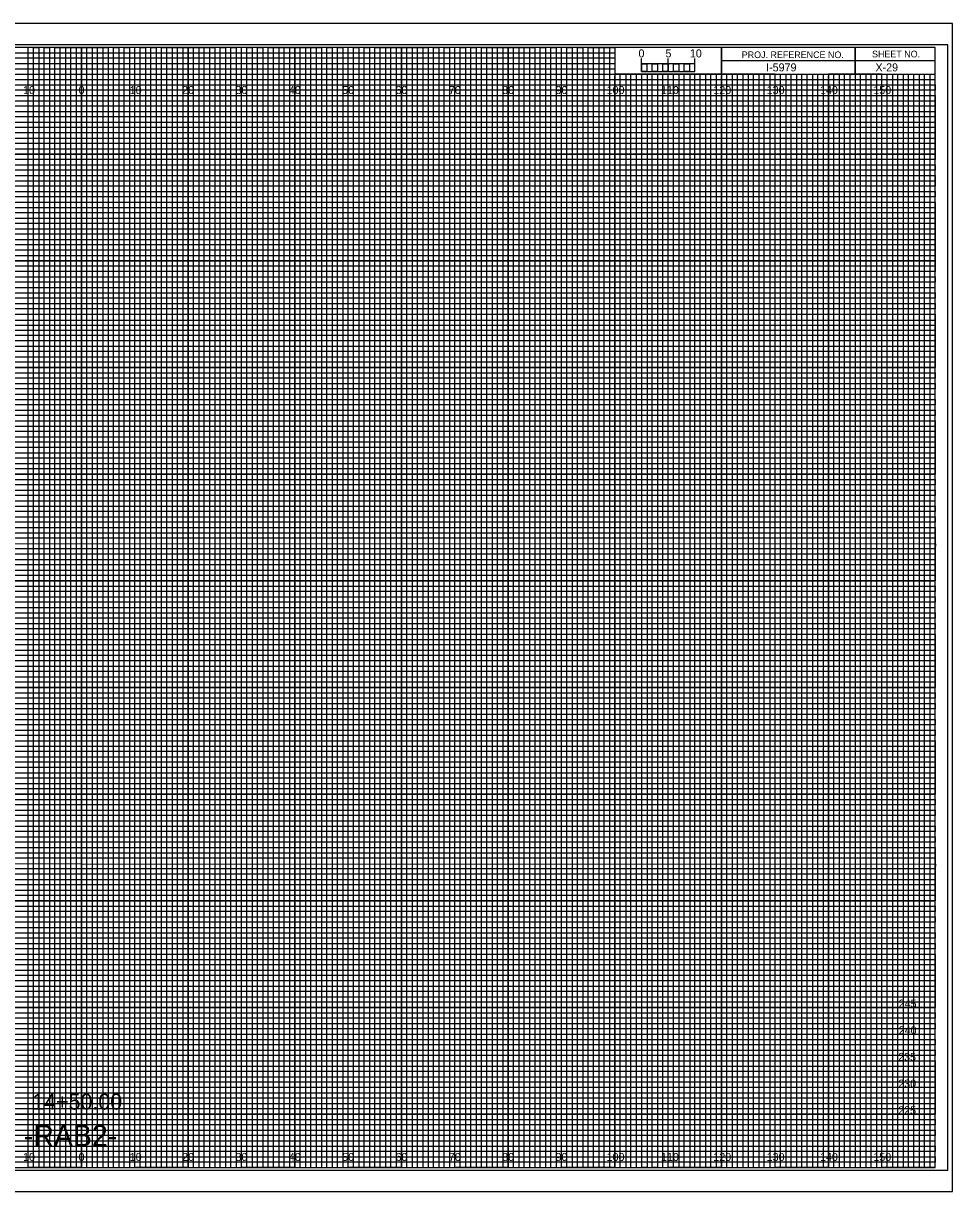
# Model space of a CAD drawing. Extents: x -13 to 323, y -5 to 654.
# Drawn here: x 149.1 to 323.3, y 435.5 to 654.5 of the extents above; entities that cross this region are included whole.
import ezdxf

# ---------------------------------------------------------------- set-up
doc = ezdxf.new("R2010")
doc.units = 0
for name, color, linetype in [('Exist CMT Pavement', 7, 'Continuous'), ('Exist Cross Section Cell', 7, 'Continuous'), ('Exist XS Center Line Elevation Label', 7, 'Continuous'), ('Exist XS Ground Line', 7, 'Continuous'), ('Prop CMT Conc Surface', 7, 'Continuous'), ('Prop CMT Concrete Structures', 7, 'Continuous'), ('Prop CMT DNC', 7, 'Continuous'), ('Prop CMT Pvmt Course 1 CG', 7, 'Continuous'), ('Prop CMT Pvmt Course 1 Wedge', 7, 'Continuous'), ('Prop CMT Pvmt Course 2', 7, 'Continuous'), ('Prop CMT Pvmt Course 2 Wedge', 7, 'Continuous'), ('Prop CMT Pvmt Course 3', 7, 'Continuous'), ('Prop CMT Pvmt Course 3 Wedge', 7, 'Continuous'), ('Prop CMT Pvmt Surface', 7, 'Continuous'), ('Prop CMT Shear Line', 7, 'Continuous'), ('Prop CMT Slope Grass', 7, 'Continuous'), ('Prop CMT Subgrade Earthwork', 7, 'Continuous')]:
    doc.layers.add(name, color=color, linetype=linetype)

msp = doc.modelspace()

# ---------------------------------------------------------------- linework, layer by layer
at = {"layer": 'Exist XS Center Line Elevation Label'}
for points in [[(145, 440), (155, 440), (155, 650), (165, 650), (165, 440), (175, 440), (175, 650), (185, 650), (185, 440), (195, 440), (195, 650), (205, 650), (205, 440), (215, 440), (215, 650), (225, 650), (225, 440), (235, 440), (235, 650), (245, 650), (245, 440), (255, 440), (255, 650), (259.93, 650), (260, 650), (260, 645), (264.99, 645), (264.99, 440), (275, 440), (275, 645), (285, 645), (285, 440), (295, 440), (295, 645), (305, 645), (305, 440), (315, 440), (315, 645)], [(0, 645), (275, 645)], [(0, 625), (320, 625), (320, 635), (0, 635)], [(0, 605), (320, 605), (320, 615), (0, 615)], [(0, 585), (320, 585), (320, 595), (0, 595)], [(0, 565), (320, 565), (320, 575), (0, 575)], [(0, 545), (320, 545), (320, 555), (0, 555)], [(0, 525), (320, 525), (320, 535), (0, 535)], [(0, 505), (320, 505), (320, 515), (0, 515)], [(0, 485), (320, 485), (320, 495), (0, 495)], [(0, 465), (320, 465), (320, 475), (0, 475)], [(0, 445), (320, 445), (320, 455), (0, 455)]]:
    msp.add_lwpolyline(points, dxfattribs=at)
at = {"layer": 'Exist XS Ground Line'}
for p, q in [((150, 650), (140, 650)), ((150, 440), (150, 650)), ((170, 650), (160, 650)), ((160, 650), (160, 440)), ((170, 440), (170, 650)), ((190, 650), (180, 650)), ((180, 650), (180, 440)), ((190, 440), (190, 650)), ((210, 650), (200, 650)), ((200, 650), (200, 440)), ((210, 440), (210, 650)), ((230, 650), (220, 650)), ((220, 650), (220, 440)), ((230, 440), (230, 650)), ((250, 650), (240, 650)), ((240, 650), (240, 440)), ((250, 440), (250, 650)), ((260, 650), (260, 440)), ((270, 440), (270, 645)), ((290, 645), (280, 645)), ((280, 645), (280, 440)), ((290, 440), (290, 645)), ((310, 645), (300, 645)), ((300, 645), (300, 440)), ((310, 440), (310, 645)), ((160, 440), (150, 440)), ((180, 440), (170, 440)), ((200, 440), (190, 440)), ((220, 440), (210, 440)), ((240, 440), (230, 440)), ((260, 440), (250, 440)), ((280, 440), (270, 440)), ((300, 440), (290, 440)), ((320, 440), (310, 440)), ((320, 440), (320, 440))]:
    msp.add_line(p, q, dxfattribs=at)
for points in [[(0, 640), (320, 640), (320, 630), (0, 630)], [(0, 620), (320, 620), (320, 610), (0, 610)], [(0, 600), (320, 600), (320, 590), (0, 590)], [(0, 580), (320, 580), (320, 570), (0, 570)], [(0, 560), (320, 560), (320, 550), (0, 550)], [(0, 540), (320, 540), (320, 530), (0, 530)], [(0, 520), (320, 520), (320, 510), (0, 510)], [(0, 500), (320, 500), (320, 490), (0, 490)], [(0, 480), (320, 480), (320, 470), (0, 470)], [(0, 460), (320, 460), (320, 450), (0, 450)]]:
    msp.add_lwpolyline(points, dxfattribs=at)
at = {"layer": 'Prop CMT Conc Surface'}
msp.add_lwpolyline([(-13.4, 435.5), (323.3, 435.5), (323.3, 654.5), (-13.4, 654.5)], close=True, dxfattribs=at)
at = {"layer": 'Prop CMT Concrete Structures'}
for p, q in [((305, 650), (305, 645)), ((305, 645), (305, 650)), ((280, 647.5), (280, 645)), ((320, 647.49), (280, 647.49)), ((280, 645), (320, 645))]:
    msp.add_line(p, q, dxfattribs=at)
for points in [[(320, 650), (0, 650), (0, 440), (320, 440)], [(280, 650), (260, 650), (260, 645.03), (280, 645.03)], [(320, 650), (280, 650), (280, 645), (320, 645)]]:
    msp.add_lwpolyline(points, close=True, dxfattribs=at)
at = {"layer": 'Prop CMT DNC'}
for p, q in [((267, 645), (266.01, 645)), ((266.01, 645), (266.01, 440)), ((267, 440), (267, 645)), ((269, 645), (268, 645)), ((268, 645), (268, 440)), ((269, 440), (269, 645)), ((266.01, 440), (265, 440)), ((268, 440), (267, 440))]:
    msp.add_line(p, q, dxfattribs=at)
for points in [[(150, 440), (151, 440), (151, 650), (152, 650), (152, 440)], [(152, 440), (153, 440), (153, 650), (154, 650), (154, 440)], [(155, 440), (156, 440), (156, 650), (157, 650), (157, 440)], [(157, 440), (158, 440), (158, 650), (159, 650), (159, 440)], [(160, 440), (161, 440), (161, 650), (162, 650), (162, 440)], [(162, 440), (163, 440), (163, 650), (164, 650), (164, 440)], [(165, 440), (166, 440), (166, 650), (167, 650), (167, 440)], [(167, 440), (168, 440), (168, 650), (169, 650), (169, 440)], [(170, 440), (171, 440), (171, 650), (172, 650), (172, 440)], [(172, 440), (173, 440), (173, 650), (174, 650), (174, 440)], [(175, 440), (176, 440), (176, 650), (177, 650), (177, 440)], [(177, 440), (178, 440), (178, 650), (179, 650), (179, 440)], [(180, 440), (181, 440), (181, 650), (182, 650), (182, 440)], [(182, 440), (183, 440), (183, 650), (184, 650), (184, 440)], [(185, 440), (186, 440), (186, 650), (187, 650), (187, 440)], [(187, 440), (188, 440), (188, 650), (189, 650), (189, 440)], [(190, 440), (191, 440), (191, 650), (192, 650), (192, 440)], [(192, 440), (193, 440), (193, 650), (194, 650), (194, 440)], [(195, 440), (196, 440), (196, 650), (197, 650), (197, 440)], [(197, 440), (198, 440), (198, 650), (199, 650), (199, 440)], [(200, 440), (201, 440), (201, 650), (202, 650), (202, 440)], [(202, 440), (203, 440), (203, 650), (204, 650), (204, 440)], [(205, 440), (206, 440), (206, 650), (207, 650), (207, 440)], [(207, 440), (208, 440), (208, 650), (209, 650), (209, 440)], [(210, 440), (211, 440), (211, 650), (212, 650), (212, 440)], [(212, 440), (213, 440), (213, 650), (214, 650), (214, 440)], [(215, 440), (216, 440), (216, 650), (217, 650), (217, 440)], [(217, 440), (218, 440), (218, 650), (219, 650), (219, 440)], [(220, 440), (221, 440), (221, 650), (222, 650), (222, 440)], [(222, 440), (223, 440), (223, 650), (224, 650), (224, 440)], [(225, 440), (226, 440), (226, 650), (227, 650), (227, 440)], [(227, 440), (228, 440), (228, 650), (229, 650), (229, 440)], [(230, 440), (231, 440), (231, 650), (232, 650), (232, 440)], [(232, 440), (233, 440), (233, 650), (234, 650), (234, 440)], [(235, 440), (236, 440), (236, 650), (237, 650), (237, 440)], [(237, 440), (238, 440), (238, 650), (239, 650), (239, 440)], [(240, 440), (241, 440), (241, 650), (242, 650), (242, 440)], [(242, 440), (243, 440), (243, 650), (244, 650), (244, 440)], [(245, 440), (246, 440), (246, 650), (247, 650), (247, 440)], [(247, 440), (248, 440), (248, 650), (249, 650), (249, 440)], [(250, 440), (251, 440), (251, 650), (252, 650), (252, 440)], [(252, 440), (253, 440), (253, 650), (254, 650), (254, 440)], [(255, 440), (256, 440), (256, 650), (257, 650), (257, 440)], [(257, 440), (258, 440), (258, 650), (259, 650), (259, 440)], [(260, 440), (261, 440), (261, 645), (262.02, 645), (262.02, 440)], [(262, 440), (263, 440), (263, 645), (263.99, 645), (263.99, 440)], [(270, 440), (270.98, 440), (270.98, 645), (272, 645), (272, 440)], [(272, 440), (273, 440), (273, 645), (274.05, 645), (274.05, 440)], [(275, 440), (276, 440), (276, 645), (277, 645), (277, 440)], [(277, 440), (278, 440), (278, 645), (279, 645), (279, 440)], [(280, 440), (281, 440), (281, 645), (282, 645), (282, 440)], [(282, 440), (283, 440), (283, 645), (284, 645), (284, 440)], [(285, 440), (286, 440), (286, 645), (287, 645), (287, 440)], [(287, 440), (288, 440), (288, 645), (289, 645), (289, 440)], [(290, 440), (291, 440), (291, 645), (292, 645), (292, 440)], [(292, 440), (293, 440), (293, 645), (294, 645), (294, 440)], [(295, 440), (296, 440), (296, 645), (297, 645), (297, 440)], [(297, 440), (298, 440), (298, 645), (299, 645), (299, 440)], [(300, 440), (301, 440), (301, 645), (302, 645), (302, 440)], [(302, 440), (303, 440), (303, 645), (304, 645), (304, 440)], [(305, 440), (306, 440), (306, 645), (307, 645), (307, 440)], [(307, 440), (308, 440), (308, 645), (309, 645), (309, 440)], [(310, 440), (311, 440), (311, 645), (312, 645), (312, 440)], [(312, 440), (313, 440), (313, 645), (314, 645), (314, 440)], [(315, 440), (316, 440), (316, 645), (317, 645), (317, 440)], [(317, 440), (318, 440), (318, 645), (319, 645), (319, 440)]]:
    msp.add_lwpolyline(points, dxfattribs=at)
at = {"layer": 'Prop CMT Pvmt Course 1 Wedge'}
for p, q in [((323.3, 654.5), (-13.4, 654.5)), ((-13.4, 435.5), (323.3, 435.5))]:
    msp.add_line(p, q, dxfattribs=at)
at = {"layer": 'Prop CMT Pvmt Course 2'}
msp.add_lwpolyline([(-10.8, 439.5), (322.4, 439.5), (322.4, 650.5), (-10.8, 650.5)], close=True, dxfattribs=at)
at = {"layer": 'Prop CMT Pvmt Course 3'}
for p, q in [((150, 440), (150, 650)), ((160, 440), (160, 650)), ((170, 440), (170, 650)), ((180, 440), (180, 650)), ((190, 440), (190, 650)), ((200, 440), (200, 650)), ((210, 440), (210, 650)), ((220, 440), (220, 650)), ((230, 440), (230, 650)), ((240, 440), (240, 650)), ((250, 440), (250, 650)), ((260, 440), (260, 644.69)), ((270, 440), (270, 644.69)), ((280, 440), (280, 644.69)), ((290, 440), (290, 644.69)), ((300, 440), (300, 644.69)), ((310, 440), (310, 644.69)), ((0, 640), (320, 640)), ((0, 630), (320, 630)), ((0, 620), (320, 620)), ((0, 610), (320, 610)), ((0, 600), (320, 600)), ((0, 590), (320, 590)), ((0, 580), (320, 580)), ((0, 570), (320, 570)), ((0, 560), (320, 560)), ((0, 550), (320, 550)), ((0, 540), (320, 540)), ((0, 530), (320, 530)), ((0, 520), (320, 520)), ((0, 510), (320, 510)), ((0, 500), (320, 500)), ((0, 490), (320, 490)), ((0, 480), (320, 480)), ((0, 470), (320, 470)), ((0, 460), (320, 460)), ((0, 450), (320, 450))]:
    msp.add_line(p, q, dxfattribs=at)
at = {"layer": 'Prop CMT Slope Grass'}
for p, q in [((265, 645.49), (265, 647.9)), ((265, 646.9), (265, 647.9)), ((270, 645.49), (270, 647.9)), ((275, 645.49), (275, 647.9)), ((275, 646.9), (275, 647.9))]:
    msp.add_line(p, q, dxfattribs=at)
for points in [[(275, 646.9), (265, 646.9), (265, 645.49), (275, 645.49)], [(265, 646.9), (266, 646.9), (266, 645.49), (265, 645.49)], [(267, 646.9), (268, 646.9), (268, 645.49), (267, 645.49)], [(269, 646.9), (270, 646.9), (270, 645.49), (269, 645.49)], [(271, 646.9), (272, 646.9), (272, 645.49), (271, 645.49)], [(273, 646.9), (274, 646.9), (274, 645.49), (273, 645.49)]]:
    msp.add_lwpolyline(points, close=True, dxfattribs=at)
at = {"layer": 'Prop CMT Subgrade Earthwork'}
for p, q in [((0, 649), (260, 649)), ((260, 649), (260, 647.98)), ((260, 647.98), (0, 647.98)), ((0, 647), (260, 647)), ((260, 647), (260, 645.89)), ((260, 645.89), (0, 645.89)), ((0, 644), (320, 644))]:
    msp.add_line(p, q, dxfattribs=at)
for points in [[(0, 643), (270, 643), (320, 643), (320, 642), (0, 642)], [(0, 641), (320, 641), (320, 639), (0, 639)], [(0, 638), (320, 638), (320, 637), (0, 636.98)], [(0, 636), (320, 636), (320, 634), (0, 634)], [(0, 633), (320, 633), (320, 632), (0, 632)], [(0, 631), (320, 631), (320, 629), (0, 629)], [(0, 628), (320, 628), (320, 627), (0, 627)], [(0, 626), (320, 626), (320, 624), (0, 624)], [(0, 623), (320, 623), (320, 622), (0, 622)], [(0, 621), (320, 621), (320, 619), (0, 619)], [(0, 618), (320, 618), (320, 617), (0, 617)], [(0, 616), (320, 616), (320, 613.95), (320, 613), (320, 612), (0, 612)], [(0, 614), (320, 614), (320, 613), (0, 613)], [(0, 611), (320, 611), (320, 609), (0, 609.03)], [(0, 609.03), (320, 609), (320, 608), (0, 608)], [(0, 607), (320, 607), (320, 606), (0, 606)], [(0, 604), (320, 604), (320, 603), (0, 603)], [(0, 602), (320, 602), (320, 601), (0, 601)], [(-0.07, 598.89), (320, 598.89), (320, 597.88), (-0.07, 597.88)], [(0, 597), (320, 597), (320, 596), (0, 596)], [(0, 594), (320, 594), (320, 593), (0, 593)], [(0, 592), (320, 592), (320, 591), (0, 591)], [(0, 589), (320, 589), (320, 588), (0, 588)], [(0, 587), (320, 587), (320, 586), (0, 586)], [(0, 584), (320, 584), (320, 583), (0, 583)], [(0, 582), (320, 582), (320, 581), (0, 581)], [(0, 579), (320, 579), (319.99, 577.98), (0, 578)], [(0, 577), (320, 577), (320, 576), (0, 576)], [(0, 574), (320, 574), (320, 573), (0, 573)], [(0, 572), (320, 572), (320, 571), (0, 571)], [(0, 569), (320, 569), (320, 568), (0, 568)], [(0, 567), (320, 567), (320, 566), (0, 566)], [(0, 564), (320, 564), (320, 563), (0, 563)], [(0, 562), (320, 562), (320, 561), (0, 561)], [(0, 559), (320, 559), (320, 558), (0, 558)], [(0, 556.99), (320.07, 556.91), (320, 556), (0, 556)], [(0, 554), (320, 554), (320, 553), (0, 553)], [(0, 552), (320, 552), (320, 551), (0, 551)], [(0, 549), (320, 549), (320, 548), (0, 548)], [(0, 547), (320, 547), (320, 546), (0, 546)], [(0, 544), (320, 544), (320, 543), (0, 543)], [(0, 542), (320, 542), (320, 541), (0, 541)], [(0, 539), (320, 539), (320, 538), (0, 538)], [(0, 537), (320, 537), (320, 536), (0, 536)], [(0, 534), (320, 534), (320, 533), (0, 533)], [(0, 532), (320, 532), (320, 531), (0, 531)], [(0, 529), (320, 529), (320, 528), (0, 528)], [(0, 527), (320, 527), (320, 526), (0, 526)], [(0, 524), (320, 524), (320, 523), (0, 523)], [(0, 522), (320, 522), (320, 521), (0, 521)], [(0, 519), (320, 519), (319.99, 517.98), (0, 518)], [(0, 517), (320, 517), (320, 516), (0, 516)], [(0, 514), (320, 514), (320, 513), (0, 513)], [(0, 512), (320, 512), (320, 511), (0, 511)], [(0, 509), (320, 509), (320, 508), (0, 508)], [(0, 507), (320, 507), (320, 506), (0, 506)], [(0, 504), (320, 504), (320, 503), (0, 503)], [(0, 502), (320, 502), (320, 501), (0, 501)], [(0, 499), (320, 499), (320, 498), (0, 498)], [(0, 496.99), (320.07, 496.91), (320, 496), (0, 496)], [(0, 494), (320, 494), (320, 493), (0, 493)], [(0, 492), (320, 492), (320, 491), (0, 491)], [(0, 489), (320, 489), (320, 488), (0, 488)], [(0, 487), (320, 487), (320, 486), (0, 486)], [(0, 484), (320, 484), (320, 483), (0, 483)], [(0, 482), (320, 482), (320, 481), (0, 481)], [(0, 479), (320, 479), (320, 478), (0, 478)], [(0, 477), (320, 477), (320, 476), (0, 476)], [(0, 474), (320, 474), (320, 473), (0, 473)], [(0, 472), (320, 472), (320, 471), (0, 471)], [(0, 469), (320, 469), (320, 468), (0, 468)], [(0, 467), (320, 467), (320, 466), (0, 466)], [(0, 464), (320, 464), (320, 463), (0, 463)], [(0, 462), (320, 462), (320, 461), (0, 461)], [(0, 459), (320, 459), (320, 458), (0, 458)], [(0, 457), (320, 457), (320, 456), (0, 456)], [(0, 454), (320, 454), (320, 453), (0, 453)], [(0, 452), (320, 452), (320, 451), (0, 451)], [(0, 449), (320, 449), (320, 448), (0, 448)], [(0, 447), (320, 447), (320, 446), (0, 446)], [(0, 444), (320, 444), (320, 443), (0, 443)], [(0, 442), (320, 442), (320, 441), (0, 441)]]:
    msp.add_lwpolyline(points, dxfattribs=at)

# ---------------------------------------------------------------- texts
at = {"layer": 'Exist CMT Pavement'}
msp.add_text('I-5979', height=1.5, dxfattribs=at).set_placement((288.34, 645.5))
at = {"layer": 'Exist Cross Section Cell'}
for s, p in [('10', (149.04, 641.25)), ('0', (159.45, 641.25)), ('0', (159.45, 641.25)), ('10', (169.04, 641.25)), ('20', (178.86, 641.25)), ('30', (188.86, 641.25)), ('40', (198.86, 641.25)), ('50', (208.86, 641.25)), ('60', (218.86, 641.25)), ('70', (228.86, 641.25)), ('80', (238.86, 641.25)), ('90', (248.86, 641.25)), ('100', (258.44, 641.25)), ('110', (268.62, 641.25)), ('120', (278.44, 641.25)), ('130', (288.44, 641.25)), ('140', (298.44, 641.25)), ('150', (308.44, 641.25)), ('10', (149.04, 441.25)), ('0', (159.45, 441.25)), ('0', (159.45, 441.25)), ('10', (169.04, 441.25)), ('20', (178.86, 441.25)), ('30', (188.86, 441.25)), ('40', (198.86, 441.25)), ('50', (208.86, 441.25)), ('60', (218.86, 441.25)), ('70', (228.86, 441.25)), ('80', (238.86, 441.25)), ('90', (248.86, 441.25)), ('100', (258.44, 441.25)), ('110', (268.62, 441.25)), ('120', (278.44, 441.25)), ('130', (288.44, 441.25)), ('140', (298.44, 441.25)), ('150', (308.44, 441.25))]:
    msp.add_text(s, height=1.5, dxfattribs=at).set_placement(p)
at = {"layer": 'Prop CMT Concrete Structures'}
for s, p in [('PROJ. REFERENCE NO.', (283.77, 647.99)), ('SHEET NO.', (308.19, 648.12))]:
    msp.add_text(s, height=1.25, dxfattribs=at).set_placement(p)
at = {"layer": 'Prop CMT Pvmt Course 1 CG'}
for s, p in [('5', (269.47, 648.12)), ('10', (274.04, 648.12))]:
    msp.add_text(s, height=1.5, dxfattribs=at).set_placement(p)
at = {"layer": 'Prop CMT Pvmt Course 2 Wedge'}
for s, p in [('245', (313.18, 470)), ('240', (313.19, 465)), ('235', (313.09, 460)), ('230', (313.11, 455)), ('225', (313.1, 450))]:
    msp.add_text(s, height=1.5, dxfattribs=at).set_placement(p)
at = {"layer": 'Prop CMT Pvmt Course 3 Wedge'}
msp.add_text('14+50.00', height=3, dxfattribs=at).set_placement((150.77, 450.87))
at = {"layer": 'Prop CMT Pvmt Surface'}
msp.add_text('-RAB2-', height=4, dxfattribs=at).set_placement((149.17, 444))
at = {"layer": 'Prop CMT Shear Line'}
msp.add_text('X-29', height=1.5, dxfattribs=at).set_placement((308.83, 645.5))
at = {"layer": 'Prop CMT Slope Grass'}
msp.add_text('0', height=1.5, dxfattribs=at).set_placement((264.41, 648.12))

doc.saveas('drawing.dxf')
